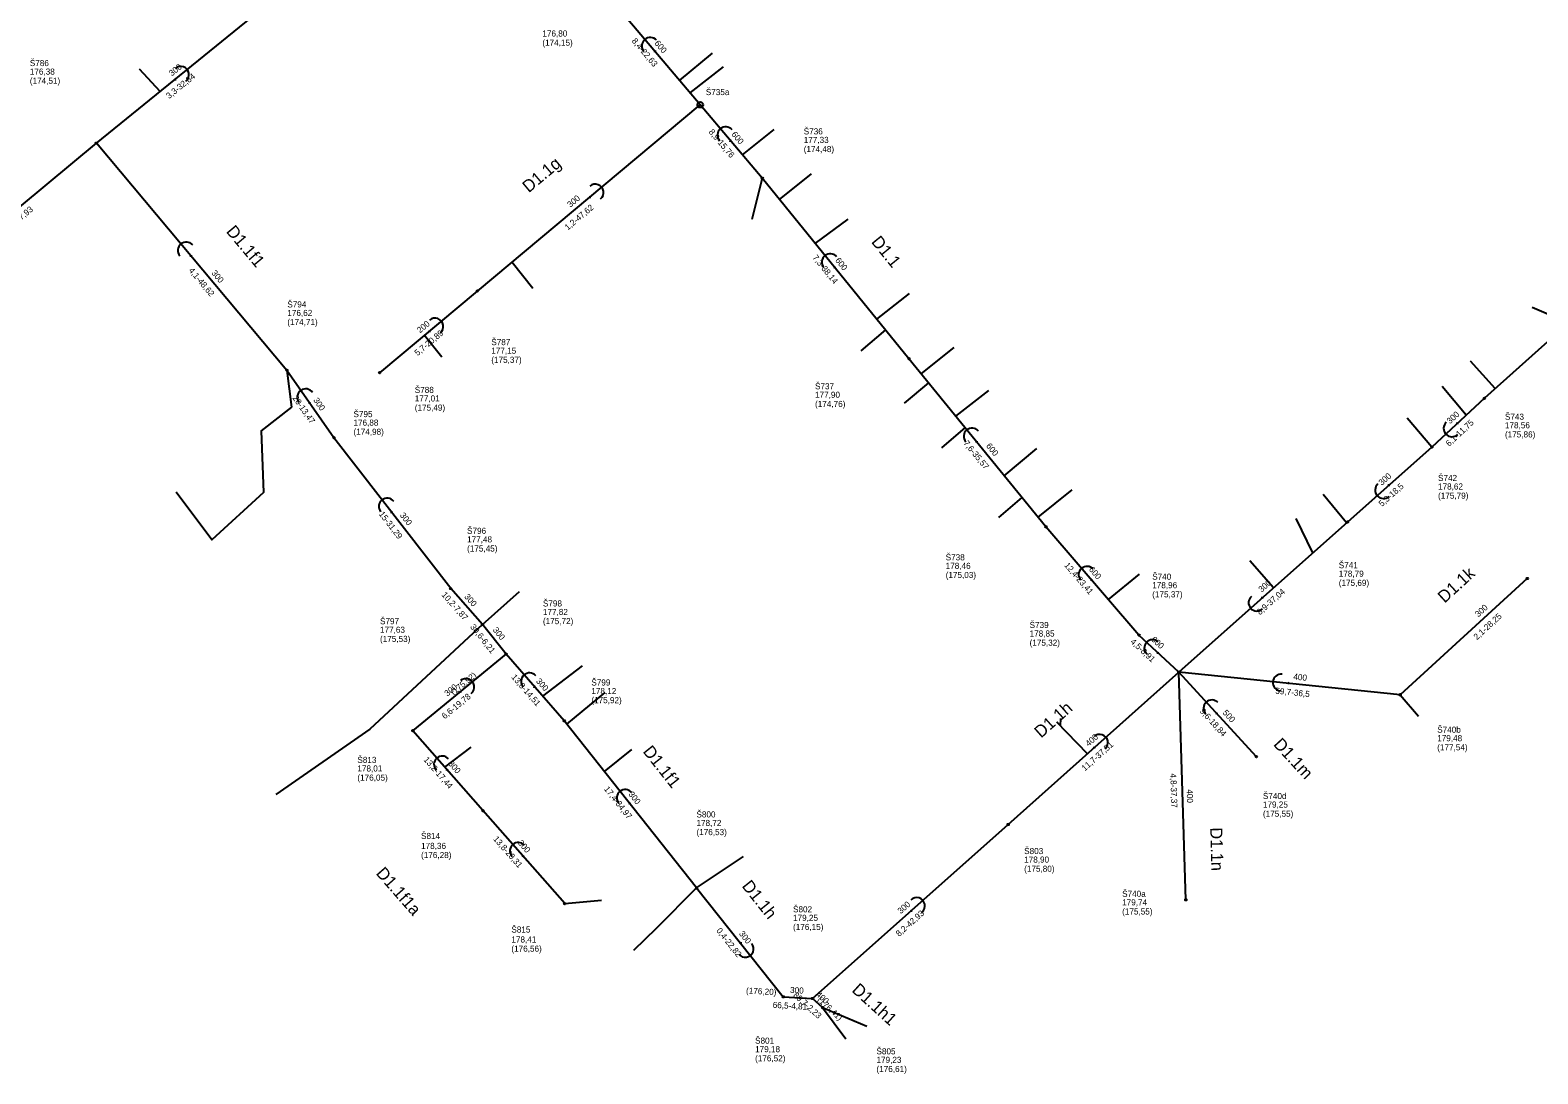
# Model space of a CAD drawing. Extents: x -548529 to -543591, y -1201432 to -1192608.
# Drawn here: x -544931.3 to -544684, y -1193806.5 to -1193635.3 of the extents above; entities that cross this region are included whole.
import ezdxf

# ---------------------------------------------------------------- set-up
doc = ezdxf.new("R2010")
doc.units = 0
for name, color, linetype in [('C3D_Bod-Značky', 7, 'Continuous'), ('C3D_Koridor', 7, 'Continuous'), ('C3D_Křižovatka', 7, 'Continuous'), ('C3D_Netisknutelná', 7, 'Continuous'), ('C3D_PP-zobrazeni v PR', 7, 'Continuous'), ('C3D_PR-Popisek', 7, 'Continuous'), ('C3D_SPR-Popisek', 7, 'Continuous'), ('C3D_Tlakove_potrubi_Popis', 7, 'Continuous'), ('C3D_ZPR-Formaty', 7, 'Continuous')]:
    doc.layers.add(name, color=color, linetype=linetype)

# ---------------------------------------------------------------- blocks, each defined once
blk = doc.blocks.new('100')
at = {"layer": 'Defpoints'}
blk.add_circle((0, 0), 0.127, dxfattribs=at)
blk = doc.blocks.new('101')
at = {"layer": 'Defpoints'}
blk.add_circle((0, 0), 0.463, dxfattribs=at)
blk = doc.blocks.new('91')
at = {"layer": 'Defpoints'}
blk.add_lwpolyline([(0.08, 0.14), (0.19, 0), (0.08, -0.14)], dxfattribs=at)
blk.add_arc((1.37, 0), 1.37, 270, 90, dxfattribs=at)
blk = doc.blocks.new('86')
at = {"layer": 'Defpoints'}
blk.add_lwpolyline([(0.08, 0.14), (0.19, 0), (0.08, -0.14)], dxfattribs=at)
blk.add_arc((1.37, 0), 1.37, 270, 90, dxfattribs=at)

msp = doc.modelspace()

# ---------------------------------------------------------------- linework, layer by layer
at = {"layer": 'C3D_Bod-Značky'}
for points in [[(-544821.397, -1193647.55), (-544836, -1193630.262)], [(-544920.416, -1193653.842), (-544894.906, -1193633.168)], [(-544857.935, -1193678.093), (-544821.397, -1193647.55)], [(-544811.23, -1193659.586), (-544821.397, -1193647.55)], [(-544949.599, -1193678.067), (-544920.416, -1193653.842)], [(-544889.181, -1193691.105), (-544920.416, -1193653.842)], [(-544644.189, -1193652.18), (-544692.822, -1193695.688)], [(-544787.177, -1193689.19), (-544811.23, -1193659.586)], [(-544873.963, -1193691.491), (-544857.935, -1193678.093)], [(-544764.713, -1193716.775), (-544787.177, -1193689.19)], [(-544881.476, -1193702.158), (-544889.181, -1193691.105)], [(-544692.822, -1193695.688), (-544701.423, -1193703.693)], [(-544862.314, -1193726.893), (-544881.476, -1193702.158)], [(-544701.423, -1193703.693), (-544715.253, -1193715.985)], [(-544715.253, -1193715.985), (-544742.935, -1193740.598)], [(-544749.461, -1193734.53), (-544764.713, -1193716.775)], [(-544685.777, -1193725.25), (-544706.62, -1193744.314)], [(-544857.104, -1193732.789), (-544862.314, -1193726.893)], [(-544853.247, -1193737.651), (-544857.104, -1193732.789)], [(-544742.935, -1193740.598), (-544749.461, -1193734.53)], [(-544868.533, -1193750.208), (-544853.247, -1193737.651)], [(-544843.705, -1193748.586), (-544853.247, -1193737.651)], [(-544770.912, -1193765.587), (-544742.935, -1193740.598)], [(-544741.775, -1193777.947), (-544742.935, -1193740.598)], [(-544706.62, -1193744.314), (-544742.935, -1193740.598)], [(-544730.2, -1193754.48), (-544742.935, -1193740.598)], [(-544857.03, -1193763.31), (-544868.533, -1193750.208)], [(-544821.99, -1193775.997), (-544843.705, -1193748.586)], [(-544843.62, -1193778.56), (-544857.03, -1193763.31)], [(-544802.982, -1193794.126), (-544770.912, -1193765.587)], [(-544821.99, -1193775.997), (-544807.787, -1193793.858)], [(-544807.787, -1193793.858), (-544802.982, -1193794.126)], [(-544801.331, -1193795.62), (-544802.982, -1193794.126)]]:
    msp.add_lwpolyline(points, dxfattribs=at)
at = {"layer": 'C3D_Koridor'}
for points in [[(-544824.779, -1193643.546), (-544819.373, -1193639.094)], [(-544909.978, -1193645.382), (-544913.355, -1193641.703)], [(-544823.076, -1193645.562), (-544817.563, -1193641.304)], [(-544814.476, -1193655.744), (-544809.282, -1193651.608)], [(-544808.403, -1193663.066), (-544803.153, -1193658.849)], [(-544811.23, -1193659.586), (-544812.954, -1193666.343)], [(-544802.544, -1193670.276), (-544797.153, -1193666.325)], [(-544852.257, -1193673.346), (-544848.869, -1193677.62)], [(-544792.463, -1193682.684), (-544787.072, -1193678.474)], [(-544680.761, -1193682.605), (-544684.99, -1193680.819)], [(-544866.605, -1193685.341), (-544863.767, -1193688.887)], [(-544791.025, -1193684.454), (-544795.078, -1193687.902)], [(-544785.16, -1193691.667), (-544779.774, -1193687.356)], [(-544889.181, -1193691.105), (-544888.437, -1193697.164)], [(-544691.045, -1193694.098), (-544695.09, -1193689.579)], [(-544783.973, -1193693.124), (-544787.94, -1193696.492)], [(-544695.779, -1193698.44), (-544699.745, -1193693.741)], [(-544779.489, -1193698.63), (-544774.066, -1193694.409)], [(-544888.437, -1193697.164), (-544893.375, -1193701.043), (-544893.029, -1193711.121), (-544901.497, -1193718.899), (-544907.361, -1193711.087)], [(-544701.423, -1193703.693), (-544705.451, -1193698.938)], [(-544777.977, -1193700.487), (-544781.834, -1193703.829)], [(-544771.549, -1193708.38), (-544766.196, -1193703.902)], [(-544766.001, -1193715.194), (-544760.419, -1193710.684)], [(-544715.41, -1193716.125), (-544719.279, -1193711.453)], [(-544768.641, -1193711.951), (-544772.484, -1193715.249)], [(-544720.934, -1193721.036), (-544723.657, -1193715.403)], [(-544727.383, -1193726.77), (-544731.274, -1193722.326)], [(-544754.465, -1193728.704), (-544749.375, -1193724.512)], [(-544857.104, -1193732.789), (-544851.057, -1193727.379)], [(-544857.104, -1193732.789), (-544875.609, -1193749.969), (-544890.988, -1193760.645)], [(-544847.209, -1193744.57), (-544840.708, -1193739.566)], [(-544843.278, -1193749.125), (-544836.967, -1193743.933)], [(-544706.62, -1193744.314), (-544703.643, -1193747.813)], [(-544762.312, -1193749.429), (-544762.269, -1193748.214)], [(-544757.918, -1193753.981), (-544762.925, -1193748.794)], [(-544863.297, -1193756.172), (-544858.972, -1193752.893)], [(-544837.12, -1193756.898), (-544832.64, -1193753.308)], [(-544821.99, -1193775.997), (-544814.327, -1193770.865)], [(-544843.62, -1193778.56), (-544837.618, -1193778.028)], [(-544821.99, -1193775.997), (-544828.61, -1193782.637), (-544832.35, -1193786.242)], [(-544801.331, -1193795.62), (-544794.103, -1193798.672)], [(-544801.331, -1193795.62), (-544797.552, -1193800.737)]]:
    msp.add_lwpolyline(points, dxfattribs=at)

# ---------------------------------------------------------------- block references
at = {"layer": 'C3D_PP-zobrazeni v PR'}
for name, p, xscale, yscale, rotation in [('101', (-544821.397, -1193647.55), 1.0000000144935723, 1.0000000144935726, 40.99999910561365), ('100', (-544920.416, -1193653.842), 1.000000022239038, 1.0000000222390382, 85.00000001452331), ('100', (-544811.23, -1193659.586), 1.0000000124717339, 1.0000000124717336, 130.0000013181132), ('100', (-544857.935, -1193678.093), 1.0000000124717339, 1.0000000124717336, -139.99999868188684), ('100', (-544787.177, -1193689.19), 1.0000000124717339, 1.0000000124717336, 130.0000013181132), ('100', (-544889.181, -1193691.105), 1.000000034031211, 1.0000000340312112, 128.00000040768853), ('100', (-544873.963, -1193691.491), 1.0000000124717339, 1.0000000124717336, -139.99999868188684), ('100', (-544692.822, -1193695.688), 1.00000000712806, 1.00000000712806, -136.99999943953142), ('100', (-544881.476, -1193702.158), 0.9999999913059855, 0.9999999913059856, 127.00000193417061), ('100', (-544701.423, -1193703.693), 1.00000000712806, 1.00000000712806, -136.99999943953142), ('100', (-544715.253, -1193715.985), 1.0000000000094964, 1.0000000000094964, -137.9999986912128), ('100', (-544764.713, -1193716.775), 1.0000000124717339, 1.0000000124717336, 130.0000013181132), ('100', (-544685.777, -1193725.25), 1.00000000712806, 1.00000000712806, 43.0000005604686), ('100', (-544862.314, -1193726.893), 1.0000000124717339, 1.0000000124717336, 130.0000013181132), ('100', (-544857.104, -1193732.789), 1.0000000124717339, 1.0000000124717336, 130.0000013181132), ('100', (-544749.461, -1193734.53), 1.0000000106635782, 1.0000000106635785, 134.00000165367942), ('100', (-544853.247, -1193737.651), 1.0000000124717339, 1.0000000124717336, 130.0000013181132), ('100', (-544706.62, -1193744.314), 1.0316957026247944, 1.0316957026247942, -156.4154111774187), ('100', (-544843.705, -1193748.586), 1.0000000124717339, 1.0000000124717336, 130.0000013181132), ('100', (-544868.533, -1193750.208), 1.0000000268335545, 1.0000000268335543, 86.00000028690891), ('100', (-544730.2, -1193754.48), 1.00000000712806, 1.00000000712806, -46.99999943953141), ('100', (-544857.03, -1193763.31), 1.0000000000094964, 1.0000000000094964, 132.0000013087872), ('100', (-544770.912, -1193765.587), 1.0000000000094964, 1.0000000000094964, -137.9999986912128), ('100', (-544821.99, -1193775.997), 1.000000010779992, 1.0000000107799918, 128.99999891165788), ('100', (-544741.775, -1193777.947), 1.00000001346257, 1.0000000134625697, 91.99999990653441), ('100', (-544843.62, -1193778.56), 1.0000000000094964, 1.0000000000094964, -47.99999869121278), ('100', (-544807.787, -1193793.858), 1.0106518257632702, 1.0106518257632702, 151.83788426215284), ('100', (-544802.982, -1193794.126), 1.0296949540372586, 1.0296949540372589, -155.86620948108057), ('100', (-544801.331, -1193795.62), 1.0000000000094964, 1.0000000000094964, 137.9999986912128)]:
    msp.add_blockref(name, p, dxfattribs=dict(at, xscale=xscale, yscale=yscale, rotation=rotation))
at = {"layer": 'C3D_PP-zobrazeni v PR', "rotation": 180}
msp.add_blockref('100', (-544742.935, -1193740.598), dxfattribs=at)
at = {"layer": 'C3D_SPR-Popisek'}
for name, p, xscale, yscale, rotation in [('91', (-544828.698, -1193638.906), 1.0000000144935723, 1.0000000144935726, 130.99999910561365), ('91', (-544907.661, -1193643.505), 1.0000000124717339, 1.0000000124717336, 40.00000131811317), ('91', (-544816.313, -1193653.568), 1.0000000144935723, 1.0000000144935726, 130.99999910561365), ('91', (-544839.666, -1193662.822), 1.0000000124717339, 1.0000000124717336, 40.00000131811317), ('91', (-544904.798, -1193672.473), 1.0000000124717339, 1.0000000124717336, 130.0000013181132), ('91', (-544799.204, -1193674.388), 1.0000000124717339, 1.0000000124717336, 130.0000013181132), ('91', (-544865.949, -1193684.792), 1.0000000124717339, 1.0000000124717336, 40.00000131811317), ('91', (-544885.329, -1193696.632), 1.000000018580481, 1.000000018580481, 125.00000023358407), ('91', (-544697.123, -1193699.691), 1.00000000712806, 1.00000000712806, -136.99999943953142), ('91', (-544775.945, -1193702.982), 1.0000000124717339, 1.0000000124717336, 130.0000013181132), ('91', (-544708.338, -1193709.839), 1.0000000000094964, 1.0000000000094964, -137.9999986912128), ('91', (-544871.895, -1193714.526), 1.000000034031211, 1.0000000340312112, 128.00000040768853), ('91', (-544757.087, -1193725.652), 1.0000000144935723, 1.0000000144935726, 130.99999910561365), ('91', (-544729.094, -1193728.292), 1.0000000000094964, 1.0000000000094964, -137.9999986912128), ('91', (-544746.198, -1193737.564), 1.0000000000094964, 1.0000000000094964, 137.9999986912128), ('91', (-544860.89, -1193743.93), 1.0000000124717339, 1.0000000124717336, 40.00000131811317), ('91', (-544848.476, -1193743.118), 1.0000000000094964, 1.0000000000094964, 132.0000013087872), ('86', (-544724.778, -1193742.456), 1.0018265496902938, 1.0018265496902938, 173.92187301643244), ('86', (-544736.568, -1193747.539), 1.00000000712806, 1.00000000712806, 133.00000056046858), ('91', (-544756.924, -1193753.092), 1.0000000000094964, 1.0000000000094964, 42.000001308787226), ('91', (-544862.782, -1193756.759), 1.0000000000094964, 1.0000000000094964, 132.0000013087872), ('91', (-544832.847, -1193762.291), 1.000000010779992, 1.0000000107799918, 128.99999891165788), ('91', (-544850.325, -1193770.935), 1.0000000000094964, 1.0000000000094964, 132.0000013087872), ('91', (-544786.947, -1193779.856), 1.0000000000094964, 1.0000000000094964, 42.000001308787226), ('91', (-544814.888, -1193784.928), 1.000000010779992, 1.0000000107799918, -51.00000108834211)]:
    msp.add_blockref(name, p, dxfattribs=dict(at, xscale=xscale, yscale=yscale, rotation=rotation))

# ---------------------------------------------------------------- texts
at = {"layer": 'C3D_Křižovatka'}
for s, p in [('Š786', (-544931.336, -1193641.202)), ('Š735a', (-544820.487, -1193645.96)), ('Š736', (-544804.43, -1193652.406)), ('Š794', (-544889.111, -1193680.785)), ('Š787', (-544855.665, -1193686.973)), ('Š788', (-544868.213, -1193694.811)), ('Š737', (-544802.577, -1193694.21)), ('Š795', (-544878.266, -1193698.778)), ('Š743', (-544689.442, -1193699.208)), ('Š742', (-544700.413, -1193709.253)), ('Š796', (-544859.634, -1193717.923)), ('Š738', (-544781.153, -1193722.265)), ('Š741', (-544716.693, -1193723.555)), ('Š740', (-544747.285, -1193725.438)), ('Š798', (-544847.197, -1193729.831)), ('Š797', (-544873.914, -1193732.749)), ('Š739', (-544767.391, -1193733.37)), ('Š799', (-544839.255, -1193742.796)), ('Š740b', (-544700.55, -1193750.534)), ('Š813', (-544877.623, -1193755.498)), ('Š740d', (-544729.13, -1193761.42)), ('Š800', (-544822.02, -1193764.437)), ('Š814', (-544867.18, -1193767.97)), ('Š803', (-544768.282, -1193770.447)), ('Š740a', (-544752.215, -1193777.457)), ('Š802', (-544806.182, -1193779.996)), ('Š815', (-544852.37, -1193783.32)), ('Š801', (-544812.407, -1193801.538)), ('Š805', (-544792.501, -1193803.29))]:
    msp.add_text(s, height=1, dxfattribs=at).set_placement(p)
at = {"layer": 'C3D_Netisknutelná'}
for s, rotation, p in [('D1.1g', 39.89, (-544849.523, -1193662.064)), ('D1.1f1', 309.97, (-544899.239, -1193668.362)), ('D1.1', 309.09, (-544793.447, -1193670.061)), ('D1.1k', 42.45, (-544699.339, -1193729.371)), ('D1.1h', 41.77, (-544765.513, -1193751.51)), ('D1.1f1', 308.39, (-544830.903, -1193753.637)), ('D1.1m', 312.53, (-544727.52, -1193752.532)), ('D1.1n', 271.78, (-544737.79, -1193766.096)), ('D1.1f1a', 311.28, (-544874.684, -1193773.657)), ('D1.1h', 308.49, (-544814.669, -1193775.714)), ('D1.1h1', 317.86, (-544796.672, -1193792.926))]:
    msp.add_text(s, height=2, rotation=rotation, dxfattribs=at).set_placement(p)
at = {"layer": 'C3D_PR-Popisek'}
for s, rotation, p in [('600', 310.19, (-544828.979, -1193637.494)), ('300', 39.02, (-544908.032, -1193642.907)), ('600', 310.19, (-544816.362, -1193652.431)), ('300', 39.89, (-544842.712, -1193664.459)), ('600', 309.09, (-544799.341, -1193673.101)), ('300', 309.97, (-544901.631, -1193675.168)), ('200', 39.89, (-544867.354, -1193685.058)), ('300', 304.88, (-544884.911, -1193696.002)), ('300', 42.94, (-544698.442, -1193699.959)), ('600', 309.16, (-544774.587, -1193703.534)), ('300', 41.63, (-544709.636, -1193710.06)), ('300', 307.76, (-544870.72, -1193714.89)), ('600', 310.66, (-544757.744, -1193723.809)), ('300', 41.64, (-544729.33, -1193727.57)), ('300', 311.47, (-544860.159, -1193728.281)), ('300', 42.45, (-544693.802, -1193731.638)), ('300', 308.42, (-544855.486, -1193733.704)), ('600', 317.08, (-544747.539, -1193735.357)), ('400', 354.16, (-544724.177, -1193741.812)), ('300', 39.4, (-544862.857, -1193744.633)), ('300', 311.11, (-544848.403, -1193742.132)), ('500', 312.53, (-544735.812, -1193747.323)), ('400', 41.77, (-544757.707, -1193752.859)), ('300', 311.28, (-544862.8, -1193755.672)), ('300', 308.39, (-544833.248, -1193760.662)), ('400', 271.78, (-544741.637, -1193759.836)), ('300', 311.33, (-544851.377, -1193768.673)), ('300', 41.67, (-544788.508, -1193780.314)), ('300', 308.49, (-544815.112, -1193783.525)), ('300', 356.81, (-544806.689, -1193793.217)), ('400', 317.86, (-544802.506, -1193793.609))]:
    msp.add_text(s, height=1, rotation=rotation, dxfattribs=at).set_placement(p)
at = {"layer": 'C3D_Tlakove_potrubi_Popis'}
for s, p in [('(174,15)', (-544847.29, -1193637.852)), ('176,80 ', (-544847.29, -1193636.352)), ('176,38 ', (-544931.336, -1193642.602)), ('(174,51)', (-544931.336, -1193644.102)), ('(174,48)', (-544804.43, -1193655.306)), ('177,33 ', (-544804.43, -1193653.806)), ('176,62 ', (-544889.111, -1193682.185)), ('(174,71)', (-544889.111, -1193683.685)), ('(175,37)', (-544855.665, -1193689.873)), ('177,15 ', (-544855.665, -1193688.373)), ('177,01 ', (-544868.213, -1193696.211)), ('(174,76)', (-544802.577, -1193697.11)), ('177,90 ', (-544802.577, -1193695.61)), ('(175,49)', (-544868.213, -1193697.711)), ('(174,98)', (-544878.266, -1193701.678)), ('176,88 ', (-544878.266, -1193700.178)), ('(175,86)', (-544689.442, -1193702.108)), ('178,56 ', (-544689.442, -1193700.608)), ('(175,79)', (-544700.413, -1193712.153)), ('178,62 ', (-544700.413, -1193710.653)), ('177,48 ', (-544859.634, -1193719.323)), ('(175,45)', (-544859.634, -1193720.823)), ('178,46 ', (-544781.153, -1193723.665)), ('(175,03)', (-544781.153, -1193725.165)), ('178,96 ', (-544747.285, -1193726.838)), ('(175,69)', (-544716.693, -1193726.455)), ('178,79 ', (-544716.693, -1193724.955)), ('(175,37)', (-544747.285, -1193728.338)), ('177,82 ', (-544847.197, -1193731.231)), ('177,63 ', (-544873.914, -1193734.149)), ('(175,72)', (-544847.197, -1193732.731)), ('(175,53)', (-544873.914, -1193735.649)), ('(175,32)', (-544767.391, -1193736.27)), ('178,85 ', (-544767.391, -1193734.77)), ('178,12 ', (-544839.255, -1193744.196)), ('(175,92)', (-544839.255, -1193745.696)), ('179,48 ', (-544700.55, -1193751.934)), ('(177,54)', (-544700.55, -1193753.434)), ('178,01 ', (-544877.623, -1193756.898)), ('(176,05)', (-544877.623, -1193758.398)), ('(175,55)', (-544729.13, -1193764.32)), ('179,25 ', (-544729.13, -1193762.82)), ('178,72 ', (-544822.02, -1193765.837)), ('(176,53)', (-544822.02, -1193767.337)), ('(176,28)', (-544867.18, -1193771.1)), ('178,36 ', (-544867.18, -1193769.6)), ('(175,80)', (-544768.282, -1193773.347)), ('178,90 ', (-544768.282, -1193771.847)), ('179,74 ', (-544752.215, -1193778.857)), ('179,25 ', (-544806.182, -1193781.396)), ('(175,55)', (-544752.215, -1193780.357)), ('(176,15)', (-544806.182, -1193782.896)), ('(176,56)', (-544852.37, -1193786.45)), ('178,41 ', (-544852.37, -1193784.95)), ('179,18 ', (-544812.407, -1193802.938)), ('(176,52)', (-544812.407, -1193804.438)), ('(176,61)', (-544792.501, -1193806.19)), ('179,23 ', (-544792.501, -1193804.69))]:
    msp.add_text(s, height=1, dxfattribs=at).set_placement(p)
at = {"layer": 'C3D_ZPR-Formaty'}
for s, rotation, p in [('8,4-22,63', 310.19, (-544832.701, -1193637.105)), ('3,3-32,84', 39.02, (-544908.498, -1193646.624)), ('8,9-15,76', 310.19, (-544820.084, -1193652.042)), ('9,5-37,93', 39.7, (-544935.056, -1193668.467)), ('1,2-47,62', 39.89, (-544843.116, -1193668.185)), ('7,3-38,14', 309.09, (-544803.06, -1193672.648)), ('4,1-48,62', 309.97, (-544905.358, -1193674.768)), ('5,7-20,89', 39.89, (-544867.758, -1193688.784)), ('20-13,47', 304.88, (-544888.326, -1193695.647)), ('6,1-11,75', 42.94, (-544698.594, -1193703.653)), ('7,6-35,57', 309.16, (-544778.308, -1193703.084)), ('5,3-18,5', 41.63, (-544709.618, -1193713.521)), ('15-31,29', 307.76, (-544874.154, -1193714.709)), ('12,4-23,41', 310.66, (-544761.768, -1193723.121)), ('10,2-7,87', 311.47, (-544863.886, -1193727.975)), ('8,9-37,04', 41.64, (-544729.617, -1193731.3)), ('2,1-28,25', 42.45, (-544694.039, -1193735.383)), ('30,6-6,21', 308.42, (-544859.201, -1193733.209)), ('4,5-8,91', 317.08, (-544750.96, -1193735.73)), ('  (175,92)   ', 39.4, (-544862.415, -1193744.923)), ('13,8-14,51', 311.11, (-544852.439, -1193741.469)), ('59,7-36,5', 354.16, (-544727.125, -1193744.13)), ('6,6-19,78', 39.4, (-544863.295, -1193748.359)), ('9,6-18,84', 312.53, (-544739.559, -1193747.09)), ('11,7-37,51', 41.77, (-544758.324, -1193756.892)), ('13,2-17,44', 311.28, (-544866.841, -1193755.018)), ('4,8-37,37', 271.78, (-544744.32, -1193757.221)), ('17,4-34,97', 308.39, (-544837.241, -1193759.802)), ('13,8-20,31', 311.33, (-544855.419, -1193768.022)), ('8,2-42,93', 41.67, (-544788.794, -1193784.045)), ('0,4-22,82', 308.49, (-544818.828, -1193783.033)), ('  (176,20)   ', 356.81, (-544814.653, -1193793.275)), ('66,5-4,81', 356.81, (-544809.533, -1193795.665)), ('89,7-2,23', 317.86, (-544806.257, -1193793.725)), ('  (176,41)   ', 317.86, (-544802.848, -1193793.978))]:
    msp.add_text(s, height=1, rotation=rotation, dxfattribs=at).set_placement(p)

doc.saveas('drawing.dxf')
